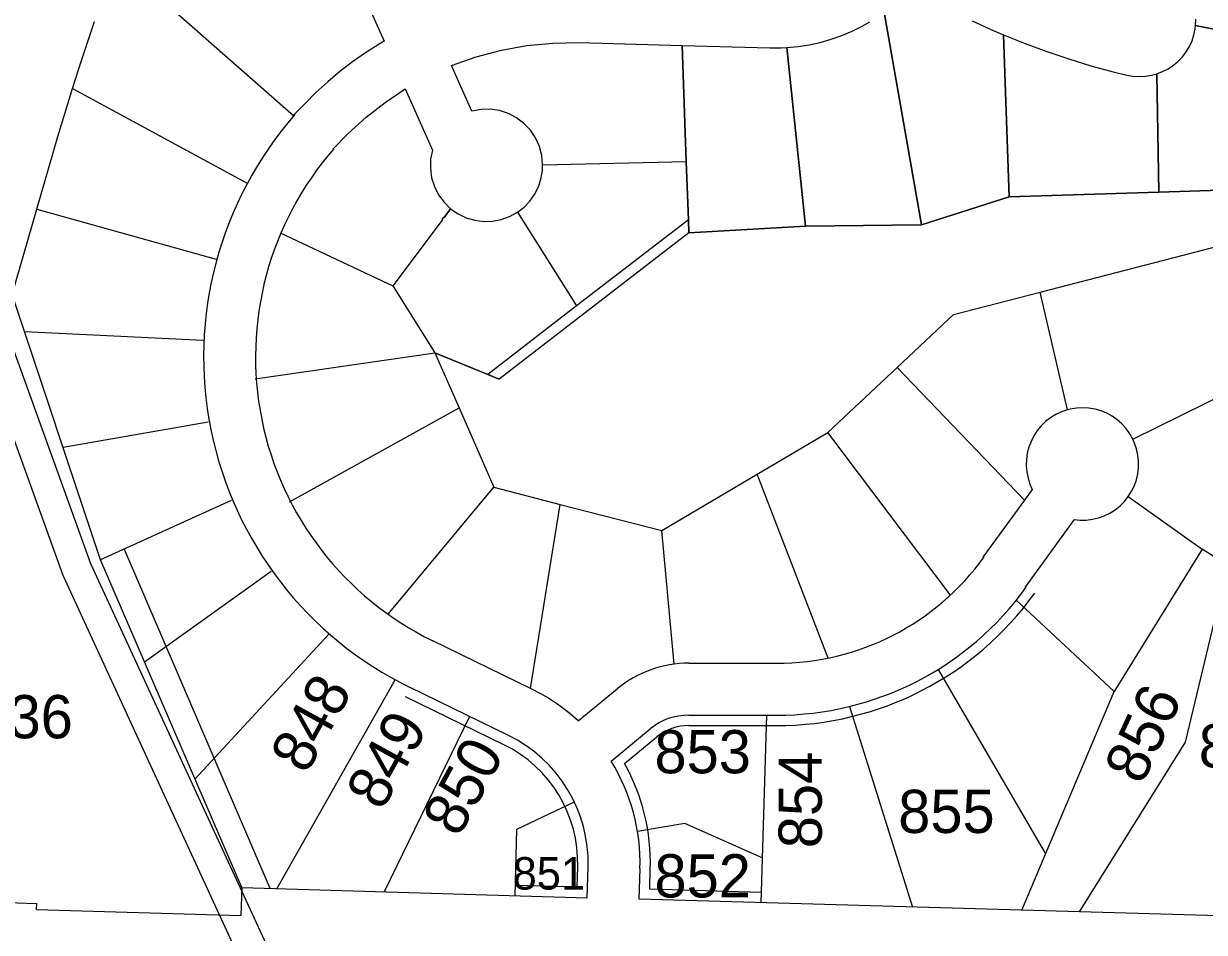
# Model space of a CAD drawing. Extents: x 582596 to 627039, y 145946 to 197316.
# Drawn here: x 618494 to 619859, y 164667 to 165717 of the extents above; entities that cross this region are included whole.
import ezdxf

# ---------------------------------------------------------------- set-up
doc = ezdxf.new("R2010")
doc.units = 0
for name, color, linetype in [('Defpoints 2', 7, 'Continuous'), ('E_RW_EasementUtility', 7, 'Continuous'), ('P_RW_PropertyLine', 7, 'Continuous')]:
    doc.layers.add(name, color=color, linetype=linetype)

msp = doc.modelspace()

# ---------------------------------------------------------------- linework, layer by layer
at = {"layer": 'E_RW_EasementUtility'}
for p, q in [((618571.7, 165092.8), (618359.3, 165680.4)), ((618326.7, 165667.5), (618539.3, 165079.5)), ((618779.1, 164717.3), (618610.4, 165109.2)), ((618774.7, 164652.4), (618571.7, 165092.8)), ((618539.3, 165079.5), (618735.6, 164653.6)), ((619049.4, 164883.5), (618935.7, 164939)), ((619134.1, 164719.1), (619134.8, 164742.5)), ((619062.6, 164721.1), (619134.1, 164719.1))]:
    msp.add_line(p, q, dxfattribs=at)
for points in [[(619263.2, 164905.8), (619364.5, 164905.7)], [(619188.9, 164861.9), (619226.3, 164892.6)], [(619347, 164712.9), (619218.1, 164716.6), (619218.7, 164740.1)]]:
    msp.add_lwpolyline(points, dxfattribs=at)
for centre, radius, start, end in [((619365, 165272.7), 367, 269.9227, 324.3464), ((619263.1, 164847.8), 58, 89.9237, 129.4252), ((618982.8, 164746.9), 152, 358.3448, 64.0237), ((618982.8, 164746.9), 236, 358.3448, 29.1754)]:
    msp.add_arc(centre, radius, start, end, dxfattribs=at)
at = {"layer": 'P_RW_PropertyLine'}
for p, q in [((618627.9, 165767.6), (618806.5, 165610.8)), ((618891, 165741.8), (618910.8, 165697)), ((619489.2, 165730.6), (619532.4, 165484.7)), ((619532.4, 165484.7), (619489.2, 165730.6)), ((618560.7, 165674.8), (618575.8, 165719.9)), ((619452.1, 165708.7), (619463.8, 165714.5)), ((619463.8, 165714.5), (619472.4, 165719.3)), ((619591, 165720.4), (619615.4, 165709.3)), ((619848.9, 165711.4), (619849.4, 165715.3)), ((619849.4, 165715.3), (619849.6, 165722.5)), ((619849.4, 165715.3), (620044.1, 165676.2)), ((620044.1, 165676.2), (619849.4, 165715.3)), ((619415.2, 165695.6), (619427.7, 165699.2)), ((619427.7, 165699.2), (619440.1, 165703.6)), ((619440.1, 165703.6), (619452.1, 165708.7)), ((619615.4, 165709.3), (619627.2, 165704.2)), ((619627.2, 165704.2), (619633.9, 165516.9)), ((619633.9, 165516.9), (619627.2, 165704.2)), ((619627.2, 165704.2), (619652.1, 165694.2)), ((619845.2, 165697.5), (619847.4, 165704.4)), ((619847.4, 165704.4), (619848.9, 165711.4)), ((618905, 165693.5), (618889.4, 165683.6)), ((618910.8, 165697), (618905, 165693.5)), ((619017.3, 165678.9), (619046.4, 165686.6)), ((619046.4, 165686.6), (619076, 165692)), ((619076, 165692), (619106, 165694.9)), ((619106, 165694.9), (619136.1, 165695.4)), ((619136.1, 165695.4), (619255.4, 165692.1)), ((619255.4, 165692.1), (619260.2, 165557.8)), ((619260.2, 165557.8), (619255.4, 165692.1)), ((619255.4, 165692.1), (619356.9, 165689.2)), ((619356.9, 165689.2), (619370, 165689.3)), ((619370, 165689.3), (619376.5, 165689.6)), ((619376.5, 165689.6), (619389.5, 165690.8)), ((619376.5, 165689.6), (619398.2, 165483.1)), ((619398.2, 165483.1), (619376.5, 165689.6)), ((619389.5, 165690.8), (619402.4, 165692.8)), ((619402.4, 165692.8), (619415.2, 165695.6)), ((619652.1, 165694.2), (619677.2, 165685)), ((619838.5, 165684.8), (619842.2, 165691)), ((619842.2, 165691), (619845.2, 165697.5)), ((618550.4, 165642.3), (618560.7, 165674.8)), ((618874.4, 165673), (618859.7, 165661.8)), ((618889.4, 165683.6), (618874.4, 165673)), ((618988.9, 165668.8), (619017.3, 165678.9)), ((619677.2, 165685), (619702.6, 165676.5)), ((619702.6, 165676.5), (619728.3, 165668.7)), ((619823.6, 165669.2), (619829.2, 165673.8)), ((619829.2, 165673.8), (619834.1, 165679)), ((619834.1, 165679), (619838.5, 165684.8)), ((618859.7, 165661.8), (618845.6, 165649.9)), ((619012.3, 165616.2), (618988.9, 165668.8)), ((619728.3, 165668.7), (619754.1, 165661.7)), ((619754.1, 165661.7), (619769.8, 165657.9)), ((619798.4, 165657.6), (619804.5, 165659.3)), ((619804.5, 165659.3), (619811.2, 165661.9)), ((619804.5, 165659.3), (619807, 165522.5)), ((619807, 165522.5), (619804.5, 165659.3)), ((619811.2, 165661.9), (619817.6, 165665.2)), ((619817.6, 165665.2), (619823.6, 165669.2)), ((618845.6, 165649.9), (618832, 165637.5)), ((619769.8, 165657.9), (619776.9, 165656.6)), ((619776.9, 165656.6), (619784.1, 165656.2)), ((619784.1, 165656.2), (619791.3, 165656.5)), ((619791.3, 165656.5), (619798.4, 165657.6)), ((618546.4, 165629.5), (618550.4, 165642.3)), ((618550.4, 165642.3), (618752.3, 165532.9)), ((618832, 165637.5), (618819, 165624.4)), ((618912, 165626.3), (618935.3, 165641.8)), ((618935.3, 165641.8), (618966.6, 165571.1)), ((618533.6, 165586.7), (618546.4, 165629.5)), ((618819, 165624.4), (618806.4, 165611.8)), ((618890, 165609), (618912, 165626.3)), ((619022.9, 165618.1), (619012.3, 165616.2)), ((619033.6, 165618.3), (619022.9, 165618.1)), ((619044.3, 165616.7), (619033.6, 165618.3)), ((618869.4, 165590.1), (618890, 165609)), ((619054.5, 165613.4), (619044.3, 165616.7)), ((619064, 165608.4), (619054.5, 165613.4)), ((619072.6, 165601.9), (619064, 165608.4)), ((618851.5, 165572.2), (618869.4, 165590.1)), ((619080, 165594.1), (619072.6, 165601.9)), ((619086, 165585.2), (619080, 165594.1)), ((618509.3, 165502.7), (618533.6, 165586.7)), ((619090.4, 165575.4), (619086, 165585.2)), ((618966.6, 165571.1), (618964.6, 165560.5)), ((619093.2, 165565), (619090.4, 165575.4)), ((619094.2, 165554.2), (619093.2, 165565)), ((618964.6, 165560.5), (618964.3, 165549.8)), ((618964.3, 165549.8), (618965.8, 165539.2)), ((619093.9, 165547), (619094.2, 165554.2)), ((619094.2, 165554.2), (619260.2, 165557.8)), ((619260.2, 165557.8), (619262.7, 165490.5)), ((619262.7, 165490.5), (619260.2, 165557.8)), ((618965.8, 165539.2), (618969, 165528.9)), ((619089.2, 165528.5), (619092.2, 165537.6)), ((619092.2, 165537.6), (619093.9, 165547)), ((618969, 165528.9), (618973.8, 165519.4)), ((619084.8, 165519.9), (619089.2, 165528.5)), ((619807, 165522.5), (619633.9, 165516.9)), ((619633.9, 165516.9), (619807, 165522.5)), ((619976.2, 165528), (619807, 165522.5)), ((619807, 165522.5), (619976.2, 165528)), ((618973.8, 165519.4), (618980.2, 165510.7)), ((618980.2, 165510.7), (618987.8, 165503.2)), ((619072.7, 165505.1), (619079.3, 165512)), ((619079.3, 165512), (619084.8, 165519.9)), ((619633.9, 165516.9), (619532.4, 165484.7)), ((619532.4, 165484.7), (619633.9, 165516.9)), ((618480, 165401.6), (618509.3, 165502.7)), ((618509.3, 165502.7), (618716.6, 165444.8)), ((618987.8, 165503.2), (618980.3, 165493.3)), ((618980.3, 165493.3), (618987.8, 165503.2)), ((618987.8, 165503.2), (618996.3, 165497.3)), ((618996.3, 165497.3), (619005.6, 165492.9)), ((619046.3, 165490.7), (619056, 165494.2)), ((619056, 165494.2), (619065.1, 165499.2)), ((619065.1, 165499.2), (619072.7, 165505.1)), ((619065.1, 165499.2), (619133.4, 165390.9)), ((618978, 165490.1), (618920.8, 165414.2)), ((618978.3, 165491.3), (618978, 165490.1)), ((618978, 165490.1), (618978.3, 165491.3)), ((618978.4, 165491.7), (618978.3, 165491.3)), ((618978.3, 165491.3), (618978.4, 165491.7)), ((618978.6, 165492.1), (618978.4, 165491.7)), ((618978.4, 165491.7), (618978.6, 165492.1)), ((618978.9, 165492.4), (618978.6, 165492.1)), ((618978.6, 165492.1), (618978.9, 165492.4)), ((618979.2, 165492.7), (618978.9, 165492.4)), ((618978.9, 165492.4), (618979.2, 165492.7)), ((618979.6, 165493), (618979.2, 165492.7)), ((618979.2, 165492.7), (618979.6, 165493)), ((618979.9, 165493.1), (618979.6, 165493)), ((618979.6, 165493), (618979.9, 165493.1)), ((618980.3, 165493.3), (618979.9, 165493.1)), ((618979.9, 165493.1), (618980.3, 165493.3)), ((619005.6, 165492.9), (619015.6, 165489.9)), ((619015.6, 165489.9), (619025.8, 165488.6)), ((619025.8, 165488.6), (619036.1, 165488.8)), ((619036.1, 165488.8), (619046.3, 165490.7)), ((619262.7, 165490.5), (619133.4, 165390.9)), ((619263.2, 165475.5), (619262.7, 165490.5)), ((619262.7, 165490.5), (619263.2, 165475.5)), ((619398.2, 165483.1), (619263.2, 165475.5)), ((619263.2, 165475.5), (619398.2, 165483.1)), ((619532.4, 165484.7), (619398.2, 165483.1)), ((619398.2, 165483.1), (619532.4, 165484.7)), ((619669.6, 165407), (619954.6, 165480.7)), ((618790.5, 165475.6), (618920.8, 165414.2)), ((619263.2, 165475.5), (619043.8, 165306.4)), ((618920.8, 165414.2), (618969.6, 165336.5)), ((618582.8, 165097.3), (618479.4, 165407.7)), ((619569.4, 165381.1), (619669.6, 165407)), ((619701.1, 165270.8), (619669.6, 165407)), ((619133.4, 165390.9), (619030.7, 165311.7)), ((619504.2, 165319.8), (619569.4, 165381.1)), ((618701.5, 165350.9), (618495.1, 165360.9)), ((619776.8, 165236.9), (620014.3, 165353.9)), ((618761.7, 165306.7), (618969.6, 165336.5)), ((618969.6, 165336.5), (618997.6, 165272.9)), ((619030.7, 165311.7), (618969.6, 165336.5)), ((618969.6, 165336.5), (619030.7, 165311.7)), ((619424, 165244.6), (619504.2, 165319.8)), ((619651.6, 165166.4), (619504.2, 165319.8)), ((619043.8, 165306.4), (619030.7, 165311.7)), ((619030.7, 165311.7), (619043.8, 165306.4)), ((618801.3, 165164.4), (618997.6, 165272.9)), ((618997.6, 165272.9), (619037.9, 165181.2)), ((619687.8, 165265.4), (619681.6, 165261.7)), ((619694.3, 165268.5), (619687.8, 165265.4)), ((619701.1, 165270.8), (619694.3, 165268.5)), ((619704.4, 165271.6), (619701.1, 165270.8)), ((619711.5, 165272.8), (619704.4, 165271.6)), ((619718.7, 165273.2), (619711.5, 165272.8)), ((619725.9, 165272.7), (619718.7, 165273.2)), ((619733, 165271.5), (619725.9, 165272.7)), ((619740, 165269.5), (619733, 165271.5)), ((619746.6, 165266.8), (619740, 165269.5)), ((619752.9, 165263.3), (619746.6, 165266.8)), ((619758.8, 165259.1), (619752.9, 165263.3)), ((618707.4, 165256.7), (618539.6, 165227.1)), ((619670.7, 165252.3), (619666.2, 165246.7)), ((619675.9, 165257.3), (619670.7, 165252.3)), ((619681.6, 165261.7), (619675.9, 165257.3)), ((619764.2, 165254.4), (619758.8, 165259.1)), ((619769.1, 165249), (619764.2, 165254.4)), ((619773.3, 165243.2), (619769.1, 165249)), ((619342.1, 165196.3), (619424, 165244.6)), ((619566, 165056.5), (619424, 165244.6)), ((619662.2, 165240.7), (619659, 165234.2)), ((619666.2, 165246.7), (619662.2, 165240.7)), ((619776.8, 165236.9), (619773.3, 165243.2)), ((619778.8, 165232.3), (619776.8, 165236.9)), ((619656.4, 165227.5), (619654.7, 165220.5)), ((619659, 165234.2), (619656.4, 165227.5)), ((619781.1, 165225.5), (619778.8, 165232.3)), ((619782.7, 165218.5), (619781.1, 165225.5)), ((619653.7, 165213.4), (619653.5, 165206.1)), ((619654.7, 165220.5), (619653.7, 165213.4)), ((619783.4, 165211.3), (619782.7, 165218.5)), ((619783.4, 165204.1), (619783.4, 165211.3)), ((619231.9, 165131.4), (619342.1, 165196.3)), ((619424.3, 164983.7), (619342.1, 165196.3)), ((619653.5, 165206.1), (619654.1, 165199)), ((619654.1, 165199), (619655.6, 165191.9)), ((619780.9, 165189.9), (619782.5, 165196.9)), ((619782.5, 165196.9), (619783.4, 165204.1)), ((618915.5, 165034.4), (619037.9, 165181.2)), ((619037.9, 165181.2), (619114.6, 165161.5)), ((619655.6, 165191.9), (619657.7, 165185)), ((619657.7, 165185), (619660.5, 165178.8)), ((619775.3, 165176.6), (619778.5, 165183.1)), ((619778.5, 165183.1), (619780.9, 165189.9)), ((619660.5, 165178.8), (619651.6, 165166.4)), ((619767, 165164.9), (619771.5, 165170.5)), ((619771.5, 165170.5), (619775.3, 165176.6)), ((619771.5, 165170.5), (619857.1, 165109.8)), ((618734.1, 165166.1), (618582.8, 165097.3)), ((619080.2, 164948.6), (619114.6, 165161.5)), ((619114.6, 165161.5), (619231.9, 165131.4)), ((619651.6, 165166.4), (619603.4, 165100.4)), ((619750.2, 165151.4), (619756.3, 165155.3)), ((619756.3, 165155.3), (619761.9, 165159.8)), ((619761.9, 165159.8), (619767, 165164.9)), ((619652.2, 165065.5), (619709.3, 165143.8)), ((619709.3, 165143.8), (619715.6, 165143.2)), ((619715.6, 165143.2), (619722.8, 165143.3)), ((619722.8, 165143.3), (619729.9, 165144.2)), ((619729.9, 165144.2), (619736.9, 165145.8)), ((619736.9, 165145.8), (619743.7, 165148.3)), ((619743.7, 165148.3), (619750.2, 165151.4)), ((619246.4, 164976.8), (619231.9, 165131.4)), ((619857.1, 165109.8), (619755.3, 164945.1)), ((619886.6, 165090.9), (619857.1, 165109.8)), ((618746.1, 164718.3), (618582.8, 165097.3)), ((619837.8, 164886.7), (619886.6, 165090.9)), ((618780.4, 165083.8), (618633.7, 164979.1)), ((619755.3, 164945.1), (619641.9, 165050.6)), ((618847.3, 165011.8), (618692, 164843.9)), ((619081, 164948.3), (618967.2, 165003.7)), ((619263.3, 164977.8), (619364.6, 164977.7)), ((619551.6, 164970.7), (619675.9, 164757.3)), ((618786.8, 164717.1), (618923.8, 164958.6)), ((619054.7, 164894.3), (618940.9, 164949.8)), ((619135.3, 164911), (619180.5, 164948.3)), ((619648.4, 164692.2), (619755.3, 164945.1)), ((619449.1, 164927.8), (619521.9, 164695.9)), ((619009.7, 164916.2), (618911, 164713.5)), ((619263.2, 164917.8), (619364.5, 164917.7)), ((619352.9, 164917.7), (619346.7, 164700.9)), ((619173.4, 164864.7), (619218.6, 164901.9)), ((619715, 164690.3), (619837.8, 164886.7)), ((619064.5, 164786), (619130.9, 164817.4)), ((619062.3, 164709.1), (619064.5, 164786)), ((619258.8, 164792.4), (619203.9, 164783.3)), ((619348.2, 164752.9), (619258.8, 164792.4)), ((619145.8, 164706.7), (619146.8, 164742.2)), ((619205.7, 164705), (619206.8, 164740.4)), ((618746.1, 164718.3), (618745.1, 164686.3)), ((618746.1, 164718.3), (619145.8, 164706.7)), ((618360.6, 164704.4), (618509.1, 164700.1)), ((619715, 164690.3), (619205.7, 164705)), ((618508.9, 164693.1), (618509.1, 164700.1)), ((618508.9, 164693.1), (618745.2, 164686.3)), ((620478.8, 164668.2), (619715.2, 164690.3))]:
    msp.add_line(p, q, dxfattribs=at)
for centre, radius, start, end in [((622033.6, 164306.8), 3879.7, 154.3609, 168.7979), ((619127.1, 165331.8), 425, 138.7292, 244.0241), ((619127.1, 165331.8), 365, 138.7292, 244.0241), ((619365, 165272.7), 295, 269.9227, 324.3464), ((619365, 165272.7), 355, 269.9227, 324.3464), ((619263.1, 164847.8), 130, 89.9238, 129.4253), ((618982.8, 164746.9), 224, 47.1235, 64.0237), ((619263.1, 164847.8), 70, 89.9238, 129.4253), ((618982.8, 164746.9), 164, 358.3448, 64.0237), ((618982.8, 164746.9), 224, 358.3448, 31.7301)]:
    msp.add_arc(centre, radius, start, end, dxfattribs=at)

# ---------------------------------------------------------------- texts
at = {"layer": 'Defpoints 2'}
for s, rotation, p in [('848', 61.2047, (618820.9, 164848.1)), ('856', 65.059, (619787.3, 164835.8)), ('849', 61.2047, (618908.4, 164805.8)), ('850', 61.2047, (618996.9, 164775)), ('854', 90, (619417, 164763.9))]:
    msp.add_text(s, height=50, rotation=rotation, dxfattribs=at).set_placement(p)
for s, height, p in [('836', 50, (618439.3, 164891)), ('857', 50, (619853, 164857.2)), ('853', 50, (619223.5, 164850.5)), ('855', 50, (619505.4, 164781.5)), ('852', 50, (619223.5, 164707)), ('851', 37.5, (619059.5, 164716.1))]:
    msp.add_text(s, height=height, dxfattribs=at).set_placement(p)

doc.saveas('drawing.dxf')
